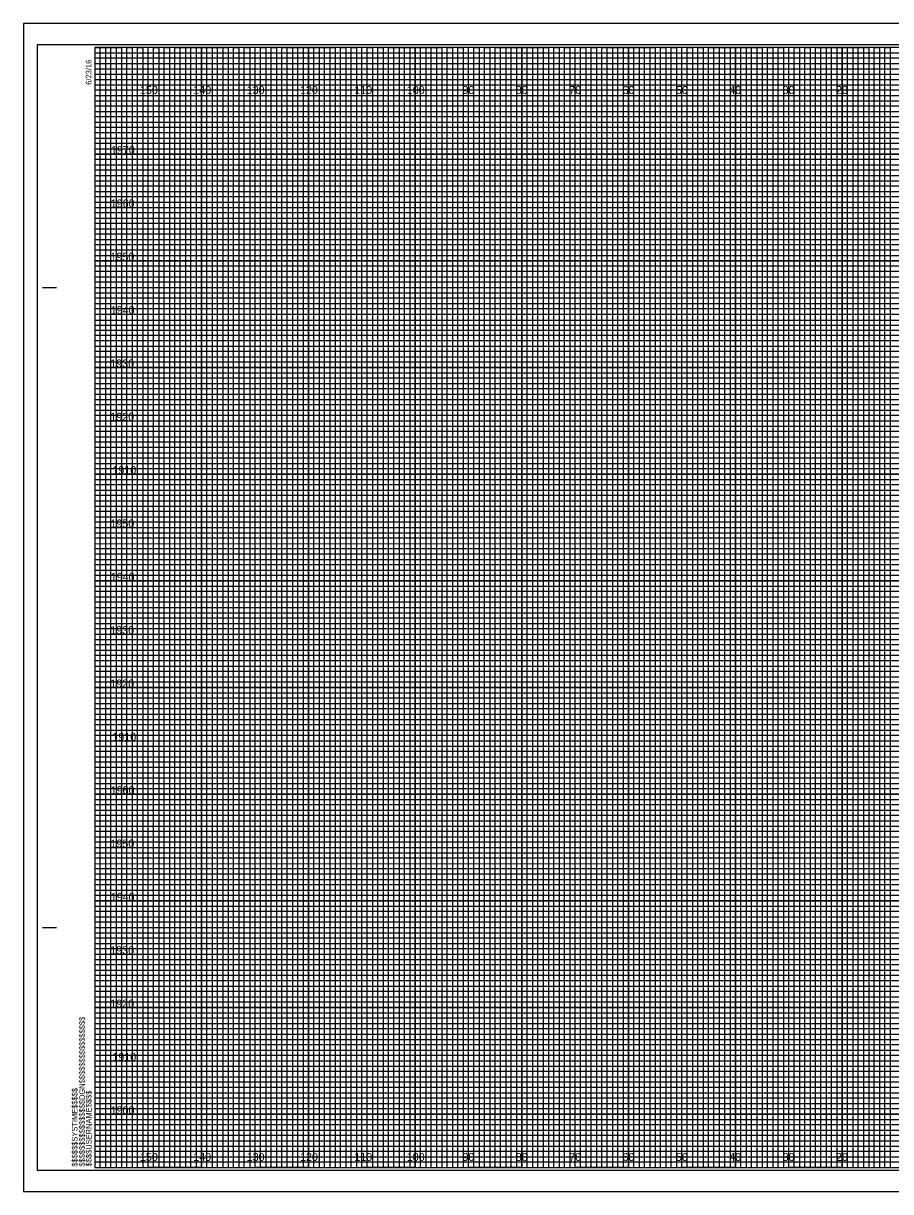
# Model space of a CAD drawing. Extents: x -13 to 323, y 215 to 434.
# Drawn here: x -13.4 to 149.1, y 215.5 to 434.5 of the extents above; entities that cross this region are included whole.
import ezdxf

# ---------------------------------------------------------------- set-up
doc = ezdxf.new("R2010")
doc.units = 0
for name, color, linetype in [('Exist Cross Section Cell', 7, 'Continuous'), ('Exist XS Center Line Elevation Label', 7, 'Continuous'), ('Exist XS Ground Line', 7, 'Continuous'), ('Prop XS Finish Grade Earthwork', 7, 'Continuous'), ('Prop XS Guardrail', 7, 'Continuous'), ('Prop XS Retaining Wall', 7, 'Continuous'), ('Prop XSC Text', 7, 'Continuous'), ('Scratch_Level_0', 7, 'Continuous'), ('Scratch_Level_5', 7, 'Continuous'), ('Scratch_Level_6', 7, 'Continuous'), ('Typical Guardrail CELL', 7, 'Continuous')]:
    doc.layers.add(name, color=color, linetype=linetype)

msp = doc.modelspace()

# ---------------------------------------------------------------- linework, layer by layer
at = {"layer": 'Exist Cross Section Cell'}
for points in [[(0, 430), (5, 430), (5, 220), (15, 220), (15, 430), (25, 430), (25, 220), (35, 220), (35, 430), (45, 430), (45, 220), (55, 220), (55, 430), (65, 430), (65, 220), (75, 220), (75, 430), (85, 430), (85, 220), (95, 220), (95, 430), (105, 430), (105, 220), (115, 220), (115, 430), (125, 430), (125, 220), (135, 220), (135, 430), (145, 430), (145, 220), (155, 220)], [(0, 425), (275, 425)], [(0, 405), (320, 405), (320, 415), (0, 415)], [(0, 385), (320, 385), (320, 395), (0, 395)], [(0, 365), (320, 365), (320, 375), (0, 375)], [(0, 345), (320, 345), (320, 355), (0, 355)], [(0, 325), (320, 325), (320, 335), (0, 335)], [(0, 305), (320, 305), (320, 315), (0, 315)], [(0, 285), (320, 285), (320, 295), (0, 295)], [(0, 265), (320, 265), (320, 275), (0, 275)], [(0, 245), (320, 245), (320, 255), (0, 255)], [(0, 225), (320, 225), (320, 235), (0, 235)]]:
    msp.add_lwpolyline(points, dxfattribs=at)
at = {"layer": 'Exist XS Center Line Elevation Label'}
for p, q in [((10, 430), (0, 430)), ((10, 220), (10, 430)), ((30, 430), (20, 430)), ((20, 430), (20, 220)), ((30, 220), (30, 430)), ((50, 430), (40, 430)), ((40, 430), (40, 220)), ((50, 220), (50, 430)), ((70, 430), (60, 430)), ((60, 430), (60, 220)), ((70, 220), (70, 430)), ((90, 430), (80, 430)), ((80, 430), (80, 220)), ((90, 220), (90, 430)), ((110, 430), (100, 430)), ((100, 430), (100, 220)), ((110, 220), (110, 430)), ((130, 430), (120, 430)), ((120, 430), (120, 220)), ((130, 220), (130, 430)), ((150, 430), (140, 430)), ((140, 430), (140, 220)), ((20, 220), (10, 220)), ((40, 220), (30, 220)), ((60, 220), (50, 220)), ((80, 220), (70, 220)), ((100, 220), (90, 220)), ((120, 220), (110, 220)), ((140, 220), (130, 220))]:
    msp.add_line(p, q, dxfattribs=at)
for points in [[(0, 420), (320, 420), (320, 410), (0, 410)], [(0, 400), (320, 400), (320, 390), (0, 390)], [(0, 380), (320, 380), (320, 370), (0, 370)], [(0, 360), (320, 360), (320, 350), (0, 350)], [(0, 340), (320, 340), (320, 330), (0, 330)], [(0, 320), (320, 320), (320, 310), (0, 310)], [(0, 300), (320, 300), (320, 290), (0, 290)], [(0, 280), (320, 280), (320, 270), (0, 270)], [(0, 260), (320, 260), (320, 250), (0, 250)], [(0, 240), (320, 240), (320, 230), (0, 230)]]:
    msp.add_lwpolyline(points, dxfattribs=at)
at = {"layer": 'Prop XS Finish Grade Earthwork'}
for p, q in [((323.3, 434.5), (-13.4, 434.5)), ((-13.4, 434.5), (-13.4, 215.5)), ((-13.4, 215.5), (323.3, 215.5))]:
    msp.add_line(p, q, dxfattribs=at)
at = {"layer": 'Prop XS Retaining Wall'}
for points in [[(0, 220), (1, 220), (1, 430), (2, 430), (2, 220)], [(2, 220), (3, 220), (3, 430), (4, 430), (4, 220)], [(5, 220), (6, 220), (6, 430), (7, 430), (7, 220)], [(7, 220), (8, 220), (8, 430), (9, 430), (9, 220)], [(10, 220), (11, 220), (11, 430), (12, 430), (12, 220)], [(12, 220), (13, 220), (13, 430), (14, 430), (14, 220)], [(15, 220), (16, 220), (16, 430), (17, 430), (17, 220)], [(17, 220), (18, 220), (18, 430), (19, 430), (19, 220)], [(20, 220), (21, 220), (21, 430), (22, 430), (22, 220)], [(22, 220), (23, 220), (23, 430), (24, 430), (24, 220)], [(25, 220), (26, 220), (26, 430), (27, 430), (27, 220)], [(27, 220), (28, 220), (28, 430), (29, 430), (29, 220)], [(30, 220), (31, 220), (31, 430), (32, 430), (32, 220)], [(32, 220), (33, 220), (33, 430), (34, 430), (34, 220)], [(35, 220), (36, 220), (36, 430), (37, 430), (37, 220)], [(37, 220), (38, 220), (38, 430), (39, 430), (39, 220)], [(40, 220), (41, 220), (41, 430), (42, 430), (42, 220)], [(42, 220), (43, 220), (43, 430), (44, 430), (44, 220)], [(45, 220), (46, 220), (46, 430), (47, 430), (47, 220)], [(47, 220), (48, 220), (48, 430), (49, 430), (49, 220)], [(50, 220), (51, 220), (51, 430), (52, 430), (52, 220)], [(52, 220), (53, 220), (53, 430), (54, 430), (54, 220)], [(55, 220), (56, 220), (56, 430), (57, 430), (57, 220)], [(57, 220), (58, 220), (58, 430), (59, 430), (59, 220)], [(60, 220), (61, 220), (61, 430), (62, 430), (62, 220)], [(62, 220), (63, 220), (63, 430), (64, 430), (64, 220)], [(65, 220), (66, 220), (66, 430), (67, 430), (67, 220)], [(67, 220), (68, 220), (68, 430), (69, 430), (69, 220)], [(70, 220), (71, 220), (71, 430), (72, 430), (72, 220)], [(72, 220), (73, 220), (73, 430), (74, 430), (74, 220)], [(75, 220), (76, 220), (76, 430), (77, 430), (77, 220)], [(77, 220), (78, 220), (78, 430), (79, 430), (79, 220)], [(80, 220), (81, 220), (81, 430), (82, 430), (82, 220)], [(82, 220), (83, 220), (83, 430), (84, 430), (84, 220)], [(85, 220), (86, 220), (86, 430), (87, 430), (87, 220)], [(87, 220), (88, 220), (88, 430), (89, 430), (89, 220)], [(90, 220), (91, 220), (91, 430), (92, 430), (92, 220)], [(92, 220), (93, 220), (93, 430), (94, 430), (94, 220)], [(95, 220), (96, 220), (96, 430), (97, 430), (97, 220)], [(97, 220), (98, 220), (98, 430), (99, 430), (99, 220)], [(100, 220), (101, 220), (101, 430), (102, 430), (102, 220)], [(102, 220), (103, 220), (103, 430), (104, 430), (104, 220)], [(105, 220), (106, 220), (106, 430), (107, 430), (107, 220)], [(107, 220), (108, 220), (108, 430), (109, 430), (109, 220)], [(110, 220), (111, 220), (111, 430), (112, 430), (112, 220)], [(112, 220), (113, 220), (113, 430), (114, 430), (114, 220)], [(115, 220), (116, 220), (116, 430), (117, 430), (117, 220)], [(117, 220), (118, 220), (118, 430), (119, 430), (119, 220)], [(120, 220), (121, 220), (121, 430), (122, 430), (122, 220)], [(122, 220), (123, 220), (123, 430), (124, 430), (124, 220)], [(125, 220), (126, 220), (126, 430), (127, 430), (127, 220)], [(127, 220), (128, 220), (128, 430), (129, 430), (129, 220)], [(130, 220), (131, 220), (131, 430), (132, 430), (132, 220)], [(132, 220), (133, 220), (133, 430), (134, 430), (134, 220)], [(135, 220), (136, 220), (136, 430), (137, 430), (137, 220)], [(137, 220), (138, 220), (138, 430), (139, 430), (139, 220)], [(140, 220), (141, 220), (141, 430), (142, 430), (142, 220)], [(142, 220), (143, 220), (143, 430), (144, 430), (144, 220)], [(145, 220), (146, 220), (146, 430), (147, 430), (147, 220)], [(147, 220), (148, 220), (148, 430), (149, 430), (149, 220)]]:
    msp.add_lwpolyline(points, dxfattribs=at)
at = {"layer": 'Prop XSC Text'}
for p, q in [((10, 220), (10, 430)), ((20, 220), (20, 430)), ((30, 220), (30, 430)), ((40, 220), (40, 430)), ((50, 220), (50, 430)), ((60, 220), (60, 430)), ((70, 220), (70, 430)), ((80, 220), (80, 430)), ((90, 220), (90, 430)), ((100, 220), (100, 430)), ((110, 220), (110, 430)), ((120, 220), (120, 430)), ((130, 220), (130, 430)), ((140, 220), (140, 430)), ((0, 420), (320, 420)), ((0, 410), (320, 410)), ((0, 400), (320, 400)), ((0, 390), (320, 390)), ((0, 380), (320, 380)), ((0, 370), (320, 370)), ((0, 360), (320, 360)), ((0, 350), (320, 350)), ((0, 340), (320, 340)), ((0, 330), (320, 330)), ((0, 320), (320, 320)), ((0, 310), (320, 310)), ((0, 300), (320, 300)), ((0, 290), (320, 290)), ((0, 280), (320, 280)), ((0, 270), (320, 270)), ((0, 260), (320, 260)), ((0, 250), (320, 250)), ((0, 240), (320, 240)), ((0, 230), (320, 230))]:
    msp.add_line(p, q, dxfattribs=at)
at = {"layer": 'Scratch_Level_0'}
msp.add_lwpolyline([(-10.8, 219.5), (322.4, 219.5), (322.4, 430.5), (-10.8, 430.5)], close=True, dxfattribs=at)
at = {"layer": 'Scratch_Level_5'}
for p, q in [((0, 429), (260, 429)), ((260, 427.98), (0, 427.98)), ((0, 427.98), (0, 427)), ((0, 427), (260, 427)), ((260, 425.89), (0, 425.89)), ((0, 425.89), (0, 424)), ((0, 424), (320, 424))]:
    msp.add_line(p, q, dxfattribs=at)
for points in [[(0, 423), (270, 423), (320, 423), (320, 422), (0, 422)], [(0, 421), (320, 421), (320, 419), (0, 419)], [(0, 418), (320, 418), (320, 417), (0, 416.98)], [(0, 416), (320, 416), (320, 414), (0, 414)], [(0, 413), (320, 413), (320, 412), (0, 412)], [(0, 411), (320, 411), (320, 409), (0, 409)], [(0, 408), (320, 408), (320, 407), (0, 407)], [(0, 406), (320, 406), (320, 404), (0, 404)], [(0, 403), (320, 403), (320, 402), (0, 402)], [(0, 401), (320, 401), (320, 399), (0, 399)], [(0, 398), (320, 398), (320, 397), (0, 397)], [(0, 396), (320, 396), (320, 393.95), (320, 393), (320, 392), (0, 392)], [(0, 394), (320, 394), (320, 393), (0, 393)], [(0, 391), (320, 391), (320, 389), (0, 389.03)], [(0, 389.03), (320, 389), (320, 388), (0, 388)], [(0, 387), (320, 387), (320, 386), (0, 386)], [(0, 384), (320, 384), (320, 383), (0, 383)], [(0, 382), (320, 382), (320, 381), (0, 381)], [(-0.07, 378.89), (320, 378.89), (320, 377.88), (-0.07, 377.88)], [(0, 377), (320, 377), (320, 376), (0, 376)], [(0, 374), (320, 374), (320, 373), (0, 373)], [(0, 372), (320, 372), (320, 371), (0, 371)], [(0, 369), (320, 369), (320, 368), (0, 368)], [(0, 367), (320, 367), (320, 366), (0, 366)], [(0, 364), (320, 364), (320, 363), (0, 363)], [(0, 362), (320, 362), (320, 361), (0, 361)], [(0, 359), (320, 359), (319.99, 357.98), (0, 358)], [(0, 357), (320, 357), (320, 356), (0, 356)], [(0, 354), (320, 354), (320, 353), (0, 353)], [(0, 352), (320, 352), (320, 351), (0, 351)], [(0, 349), (320, 349), (320, 348), (0, 348)], [(0, 347), (320, 347), (320, 346), (0, 346)], [(0, 344), (320, 344), (320, 343), (0, 343)], [(0, 342), (320, 342), (320, 341), (0, 341)], [(0, 339), (320, 339), (320, 338), (0, 338)], [(0, 336.99), (320.07, 336.91), (320, 336), (0, 336)], [(0, 334), (320, 334), (320, 333), (0, 333)], [(0, 332), (320, 332), (320, 331), (0, 331)], [(0, 329), (320, 329), (320, 328), (0, 328)], [(0, 327), (320, 327), (320, 326), (0, 326)], [(0, 324), (320, 324), (320, 323), (0, 323)], [(0, 322), (320, 322), (320, 321), (0, 321)], [(0, 319), (320, 319), (320, 318), (0, 318)], [(0, 317), (320, 317), (320, 316), (0, 316)], [(0, 314), (320, 314), (320, 313), (0, 313)], [(0, 312), (320, 312), (320, 311), (0, 311)], [(0, 309), (320, 309), (320, 308), (0, 308)], [(0, 307), (320, 307), (320, 306), (0, 306)], [(0, 304), (320, 304), (320, 303), (0, 303)], [(0, 302), (320, 302), (320, 301), (0, 301)], [(0, 299), (320, 299), (319.99, 297.98), (0, 298)], [(0, 297), (320, 297), (320, 296), (0, 296)], [(0, 294), (320, 294), (320, 293), (0, 293)], [(0, 292), (320, 292), (320, 291), (0, 291)], [(0, 289), (320, 289), (320, 288), (0, 288)], [(0, 287), (320, 287), (320, 286), (0, 286)], [(0, 284), (320, 284), (320, 283), (0, 283)], [(0, 282), (320, 282), (320, 281), (0, 281)], [(0, 279), (320, 279), (320, 278), (0, 278)], [(0, 276.99), (320.07, 276.91), (320, 276), (0, 276)], [(0, 274), (320, 274), (320, 273), (0, 273)], [(0, 272), (320, 272), (320, 271), (0, 271)], [(0, 269), (320, 269), (320, 268), (0, 268)], [(0, 267), (320, 267), (320, 266), (0, 266)], [(0, 264), (320, 264), (320, 263), (0, 263)], [(0, 262), (320, 262), (320, 261), (0, 261)], [(0, 259), (320, 259), (320, 258), (0, 258)], [(0, 257), (320, 257), (320, 256), (0, 256)], [(0, 254), (320, 254), (320, 253), (0, 253)], [(0, 252), (320, 252), (320, 251), (0, 251)], [(0, 249), (320, 249), (320, 248), (0, 248)], [(0, 247), (320, 247), (320, 246), (0, 246)], [(0, 244), (320, 244), (320, 243), (0, 243)], [(0, 242), (320, 242), (320, 241), (0, 241)], [(0, 239), (320, 239), (320, 238), (0, 238)], [(0, 237), (320, 237), (320, 236), (0, 236)], [(0, 234), (320, 234), (320, 233), (0, 233)], [(0, 232), (320, 232), (320, 231), (0, 231)], [(0, 229), (320, 229), (320, 228), (0, 228)], [(0, 227), (320, 227), (320, 226), (0, 226)], [(0, 224), (320, 224), (320, 223), (0, 223)], [(0, 222), (320, 222), (320, 221), (0, 221)]]:
    msp.add_lwpolyline(points, dxfattribs=at)
at = {"layer": 'Scratch_Level_6'}
for p, q in [((-9.8, 385), (-7.3, 385)), ((-9.7, 385), (-7.2, 385)), ((-9.8, 265), (-7.3, 265)), ((-9.7, 265), (-7.2, 265)), ((0, 220), (0, 220)), ((0, 220), (0, 220)), ((0, 220), (0, 220)), ((0, 220), (0, 220)), ((0, 220), (0, 220)), ((0, 220), (0, 220)), ((0, 220), (0, 220))]:
    msp.add_line(p, q, dxfattribs=at)
msp.add_lwpolyline([(320, 430), (0, 430), (0, 220), (320, 220)], close=True, dxfattribs=at)
at = {"layer": 'Typical Guardrail CELL'}
msp.add_lwpolyline([(-13.4, 215.5), (323.3, 215.5), (323.3, 434.5), (-13.4, 434.5)], close=True, dxfattribs=at)

# ---------------------------------------------------------------- texts
at = {"layer": 'Exist XS Ground Line'}
for s, p in [('150', (8.44, 421.25)), ('140', (18.44, 421.25)), ('130', (28.44, 421.25)), ('120', (38.44, 421.25)), ('110', (48.62, 421.25)), ('100', (58.44, 421.25)), ('90', (68.86, 421.25)), ('80', (78.86, 421.25)), ('70', (88.86, 421.25)), ('60', (98.86, 421.25)), ('50', (108.86, 421.25)), ('40', (118.86, 421.25)), ('30', (128.86, 421.25)), ('20', (138.86, 421.25)), ('150', (8.44, 221.25)), ('140', (18.44, 221.25)), ('130', (28.44, 221.25)), ('120', (38.44, 221.25)), ('110', (48.62, 221.25)), ('100', (58.44, 221.25)), ('90', (68.86, 221.25)), ('80', (78.86, 221.25)), ('70', (88.86, 221.25)), ('60', (98.86, 221.25)), ('50', (108.86, 221.25)), ('40', (118.86, 221.25)), ('30', (128.86, 221.25)), ('20', (138.86, 221.25))]:
    msp.add_text(s, height=1.5, dxfattribs=at).set_placement(p)
at = {"layer": 'Prop XS Guardrail'}
for s, p in [('1970', (3, 410)), ('1960', (2.97, 400)), ('1950', (2.92, 390)), ('1940', (2.97, 380)), ('1930', (2.89, 370)), ('1920', (2.9, 360)), ('1910', (3.28, 350)), ('1950', (2.92, 340)), ('1940', (2.97, 330)), ('1930', (2.89, 320)), ('1920', (2.9, 310)), ('1910', (3.28, 300)), ('1900', (2.95, 290)), ('1960', (2.97, 290)), ('1950', (2.92, 280)), ('1940', (2.97, 270)), ('1930', (2.89, 260)), ('1920', (2.9, 250)), ('1910', (3.28, 240)), ('1900', (2.95, 230))]:
    msp.add_text(s, height=1.5, dxfattribs=at).set_placement(p)
at = {"layer": 'Scratch_Level_6'}
for s, p in [('6/23/16', (-0.65, 423)), ('$$$$$$$$$$$$$$$$DGN$$$$$$$$$$$$$$$$', (-1.88, 220.18)), ('$$$$$$SYSTIME$$$$$', (-3.26, 220.18)), ('$$$$USERNAME$$$$', (-0.62, 220.23))]:
    msp.add_text(s, height=1.05, rotation=90, dxfattribs=at).set_placement(p)

doc.saveas('drawing.dxf')
